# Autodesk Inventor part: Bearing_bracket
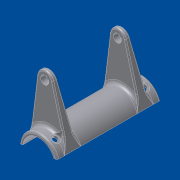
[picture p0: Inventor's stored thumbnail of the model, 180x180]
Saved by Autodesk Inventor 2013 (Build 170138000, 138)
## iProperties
Shininess: 25.0
Length Units: 11269
Angle Units: 11279
Time Units: 11290
Mass Units: 11283
Length Display Precision: 3
Angle Display Precision: 2
Created: 2001-04
Part Number: Bearing_bracket
Material: Standard
Document SubType Name: Modellieren
Designer: dl
Density: 1 g/cm^3
Density: 0.0
Volumn: 0.0
Area: 0.0
PropertySet Name: Model Information
Control State: 0
Master: False
Checked Out: False
Author: dl
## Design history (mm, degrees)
sketch "Sketch1"
  geometry: C1 r 24 at (0, 0); C2 r 20 at (0, 0)
  constraints: 2 centre point, 1 coincident
  dimensions: "d0" = 40 diameter of C2; "d1" = 4 radial gap between concentric circles of C1 C2
extrude "Extrusion1" new body sketch "Sketch1" distance "d2" = 128; taper "d3" = 0 deg
sketch "Sketch2"
  geometry: L1 (0, 0)-(0, 24); L2 (0, 0)-(-8.531, 69.478); L3 (0.95, 72.657)-(22.755, 7.63); L4 (-18.5, 70.269)-(-23.925, 1.898); A1 r 24 centre (0, 0) between (0, 24) and (22.755, 7.63); A2 r 10 centre (-8.531, 69.478) between (0.95, 72.657) and (-18.5, 70.269); 1 further point
  constraints: 8 end point, 5 point on circle, 4 tangent, 2 centre point, 1 coincident, 1 vertical, 2 other
  dimensions: "d6" = 7 deg angle of L2 L1; "d7" = 70 distance of L1.start L2.end; "d8" = 20 diameter of A2
extrude "Extrusion2" join sketch "Sketch2" stored distance "d9" = 6; taper "d10" = 0 deg
extrude "Extrusion3" join sketch "Sketch2" stored distance "d19" = 8; taper "d20" = 0 deg
sketch "Sketch5"
  geometry: C1 r 3.25 at (0, 9) reference; C2 r 5 at (0, 9)
  constraints: 1 centre point, 1 coincident
  dimensions: "d40" = 10 diameter of C2
extrude "Extrusion7" cut sketch "Sketch5" distance "d46" = 8; taper "d47" = 0 deg
sketch "Sketch6"
  geometry: C1 r 5 at (0, 0) reference; C2 r 3.25 at (0, 0)
  constraints: 1 centre point, 1 coincident
  dimensions: "d45" = 6.5 diameter of C2
extrude "Extrusion8" cut sketch "Sketch6" stored distance "d49" = 10; taper "d50" = 0 deg
body "Solid1"
workplane "Work Plane1"
workplane "Work Plane2"
workplane "Work Plane3"
workplane "Work Plane4"
workplane "Work Plane5"
workaxis "Work Axis1"
workplane "Work Plane6"
workaxis "Work Axis2"
workplane "Work Plane7"
mirror "Mirror1"
mirror "Mirror2"
fillet "Fillet1" dims "d26" = 4
fillet "Fillet2" dims "d27" = 1.5
sketch "Sketch3"
  geometry: C1 r 5 at (-8.531, 69.557)
  constraints: 1 centre point
  dimensions: "d28" = 10 diameter of C1
extrude "Extrusion4" cut sketch "Sketch3" stored distance "d29" = 8; taper "d30" = 0 deg
workaxis "Work Axis3"
workplane "Work Plane8"
workplane "Work Plane9"
sketch "Sketch4"
  geometry: L1 (-24, 0)-(24, 0) reference; L2 (0, 0)-(0, 64); C1 r 3.25 at (0, 9)
  constraints: 2 end point, 1 centre point, 1 midpoint, 1 perpendicular
  dimensions: "d34" = 6.5 diameter of C1; "d35" = 0 horizontal distance of L2.start C1.centre; "d36" = 64 distance of L2.start L2.end (= 0.5 x d2); "d37" = 55 distance of L2.end C1.centre
extrude "Extrusion5" cut sketch "Sketch4" distance "d38" = 8; taper "d39" = 0 deg
extrude "Extrusion6" cut sketch "Sketch5" stored distance "d43" = 8; taper "d44" = 0 deg
mirror "Mirror3"
fillet "Fillet3" dims "d51" = 2
workaxis "Work Axis4"
workaxis "Work Axis5"
workplane "Work Plane10"
sketch "Sketch7"
  geometry: L1 (-23.925, 1.898)-(22.755, 7.63); A1 r 24 centre (0, 0) between (-23.925, 1.898) and (22.755, 7.63) reference; A2 r 24 centre (0, 0) between (22.755, 7.63) and (-23.925, 1.898) reference; A3 r 269.736 centre (-10.118, 275.355) between (-4.075, 5.687) and (22.755, 7.63)
  constraints: 2 end point, 2 point on circle, 1 centre point, 1 tangent
other parameters: "d4" = -64 (= -0.5 x d2), "d5" = 45, "d12" = 24, "d13" = 5.5, "d14" = -5.5 (= -d13), "d15" = 5 deg, "d16" = 3 deg, "d17" = -5 deg (= -d15), "d18" = -3 deg (= -d16), "d31" = 60 deg, "d32" = 150 deg, "d33" = -23
